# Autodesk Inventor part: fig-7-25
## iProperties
Shininess: 64.0
Length Units: 11269
Angle Units: 11279
Time Units: 11290
Mass Units: 11283
Length Display Precision: 3
Angle Display Precision: 2
Compacted: True
Part Number: fig-7-25
Document SubType Name: Modeling
Created: 2002-12
Designer: deepak
Density: 1 g/cm^3
Density: 0.0
Volumn: 0.0
Area: 0.0
PropertySet Name: Model Information
Control State: 0
Master: False
Checked Out: False
Author: deepak
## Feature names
1. Loft4
